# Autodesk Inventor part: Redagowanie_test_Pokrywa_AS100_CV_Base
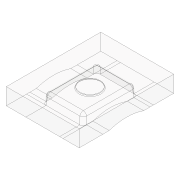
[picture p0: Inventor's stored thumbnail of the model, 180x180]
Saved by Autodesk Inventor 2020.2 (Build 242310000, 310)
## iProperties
Created: 2015-11
Part Number: Redagowanie_test_Pokrywa_AS100_CV_Base
Material: Ogólne
Document SubType Name: Modeling
Designer: F.Stasiak
Density: 1 g/cm^3
Appearance: Domyślne
Catalog Web Link: www.expertbooks.pl
Manager: www.cadconsulting.pl
Company: Fabian Stasiak CAD Consulting
Author: F.Stasiak
Subject: Zbiór ćwiczeń. Autodesk Inventor 2020. Kurs Professional
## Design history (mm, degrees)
node "Redagowanie_test_Pokrywa_AS100_MP"
feature "Bryła6::Redagowanie_test_Pokrywa_AS100_MP"
tag "Bryła wyprowadzona2"
node "Bryła2"
feature "Redagowanie_test_Pokrywa_AS100_MP_Bodies"
